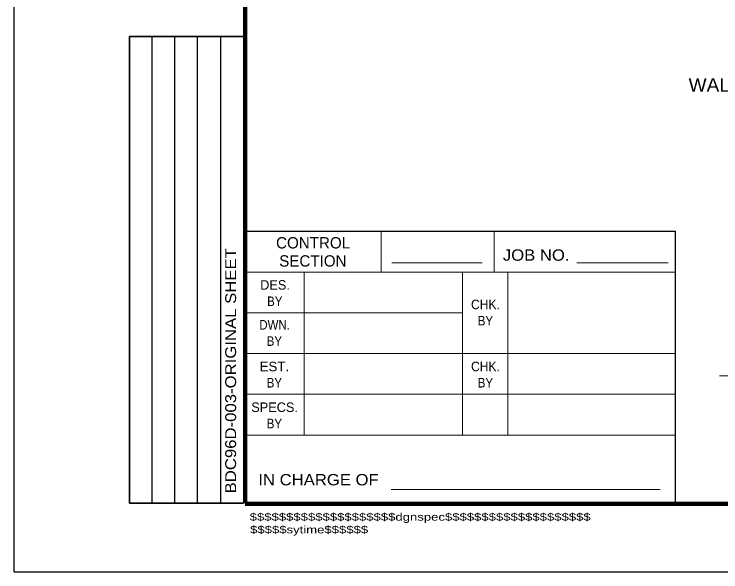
# Model space of a CAD drawing. Extents: x 312601.858 to 312602.699, y 144420.109 to 144420.704.
# Drawn here: x 312601.8578 to 312602.0138, y 144420.1095 to 144420.2326 of the extents above; entities that cross this region are included whole.
import ezdxf
from ezdxf.enums import TextEntityAlignment as Align

# ---------------------------------------------------------------- set-up
doc = ezdxf.new("R2010")
doc.units = 0
doc.header["$LTSCALE"] = 0.0012
for name, color, linetype, lineweight in [('1', 7, 'Continuous', 13), ('2', 7, 'Continuous', 13), ('39', 7, 'Continuous', 13), ('60', 7, 'Continuous', 25)]:
    doc.layers.add(name, color=color, linetype=linetype, lineweight=lineweight)

msp = doc.modelspace()

# ---------------------------------------------------------------- linework, layer by layer
at = {"layer": '1'}
msp.add_line((312602.0593, 144420.1528), (312602.0135, 144420.1528), dxfattribs=at)
at = {"layer": '39', "lineweight": 25}
for p, q in [((312601.8578, 144420.1095), (312601.8578, 144420.7035)), ((312601.9088, 144420.1847), (312602.0038, 144420.1847)), ((312602.0038, 144420.1247), (312602.0038, 144420.1847)), ((312601.8578, 144420.1095), (312602.6988, 144420.1095))]:
    msp.add_line(p, q, dxfattribs=at)
at = {"layer": '39', "lineweight": 158}
for p, q in [((312601.9088, 144420.1247), (312601.9088, 144420.6645)), ((312601.9088, 144420.1245), (312602.6838, 144420.1245))]:
    msp.add_line(p, q, dxfattribs=at)
at = {"layer": '39'}
for p, q in [((312601.9088, 144420.1247), (312601.9088, 144420.1847)), ((312601.9388, 144420.1757), (312601.9388, 144420.1847)), ((312601.9638, 144420.1757), (312601.9638, 144420.1847)), ((312601.9412, 144420.1777), (312601.9611, 144420.1777)), ((312601.982, 144420.1777), (312602.0022, 144420.1777)), ((312601.9088, 144420.1757), (312602.0038, 144420.1757)), ((312601.9218, 144420.1397), (312601.9218, 144420.1757)), ((312601.9568, 144420.1397), (312601.9568, 144420.1757)), ((312601.9668, 144420.1397), (312601.9668, 144420.1757)), ((312601.9088, 144420.1667), (312601.9568, 144420.1667)), ((312601.9088, 144420.1577), (312602.0038, 144420.1577)), ((312601.9088, 144420.1487), (312602.0038, 144420.1487)), ((312601.9088, 144420.1397), (312602.0038, 144420.1397)), ((312601.941, 144420.1277), (312602.0004, 144420.1277)), ((312601.9088, 144420.1247), (312602.0038, 144420.1247))]:
    msp.add_line(p, q, dxfattribs=at)
at = {"layer": '60'}
for p, q in [((312601.8883, 144420.1247), (312601.8883, 144420.2277)), ((312601.8933, 144420.1247), (312601.8933, 144420.2277)), ((312601.8983, 144420.1247), (312601.8983, 144420.2277)), ((312601.9034, 144420.1247), (312601.9034, 144420.2277))]:
    msp.add_line(p, q, dxfattribs=at)
at = {"layer": '60', "lineweight": 35}
msp.add_lwpolyline([(312601.9084, 144420.1247), (312601.8833, 144420.1247), (312601.8833, 144420.2277), (312601.9084, 144420.2277)], dxfattribs=at)

# ---------------------------------------------------------------- texts
at = {"layer": '1'}
for s, height, p in [('CONTROL', 0.0025, (312601.9238, 144420.1809)), ('SECTION', 0.0025, (312601.92375, 144420.1769)), ('DES.', 0.0021, (312601.9154, 144420.1718)), ('SPECS.', 0.0021, (312601.9153, 144420.1448))]:
    msp.add_text(s, height=height, dxfattribs=at).set_placement(p, align=Align.CENTER)
for s, height, width, p in [('JOB NO.', 0.0025, 1.1, (312601.97305, 144420.1782)), ('BY', 0.0021, 0.9, (312601.91535, 144420.1682)), ('CHK.', 0.0021, 0.95, (312601.96185, 144420.1675)), ('DWN.', 0.0021, 0.9, (312601.9153, 144420.163)), ('BY', 0.0021, 0.9, (312601.96185, 144420.1639)), ('BY', 0.0021, 0.9, (312601.91525, 144420.1594)), ('EST.', 0.0021, 1.05, (312601.91525, 144420.1538)), ('CHK.', 0.0021, 0.95, (312601.96185, 144420.1538)), ('BY', 0.0021, 0.9, (312601.91525, 144420.1502)), ('BY', 0.0021, 0.9, (312601.96185, 144420.1502)), ('BY', 0.0021, 0.9, (312601.91525, 144420.1412)), ('IN CHARGE OF', 0.0025, 1.1, (312601.925, 144420.1286))]:
    msp.add_text(s, height=height, dxfattribs=dict(at, width=width)).set_placement(p, align=Align.CENTER)
at = {"layer": '2'}
for s, height, width, p in [('WALKWAY GRATING', 0.003, 1.05, (312602.0067, 144420.2155)), ('$$$$$$$$$$$$$$$$$$$$dgnspec$$$$$$$$$$$$$$$$$$$$', 0.001664, 1.3, (312601.9098, 144420.1208)), ('$$$$$sytime$$$$$$', 0.001664, 1.3, (312601.9099, 144420.118))]:
    msp.add_text(s, height=height, dxfattribs=dict(at, width=width)).set_placement(p)
at = {"layer": '2', "width": 1.15}
msp.add_text('BDC96D-003-ORIGINAL SHEET', height=0.0024, rotation=90, dxfattribs=at).set_placement((312601.9068, 144420.1539), align=Align.CENTER)

doc.saveas('drawing.dxf')
